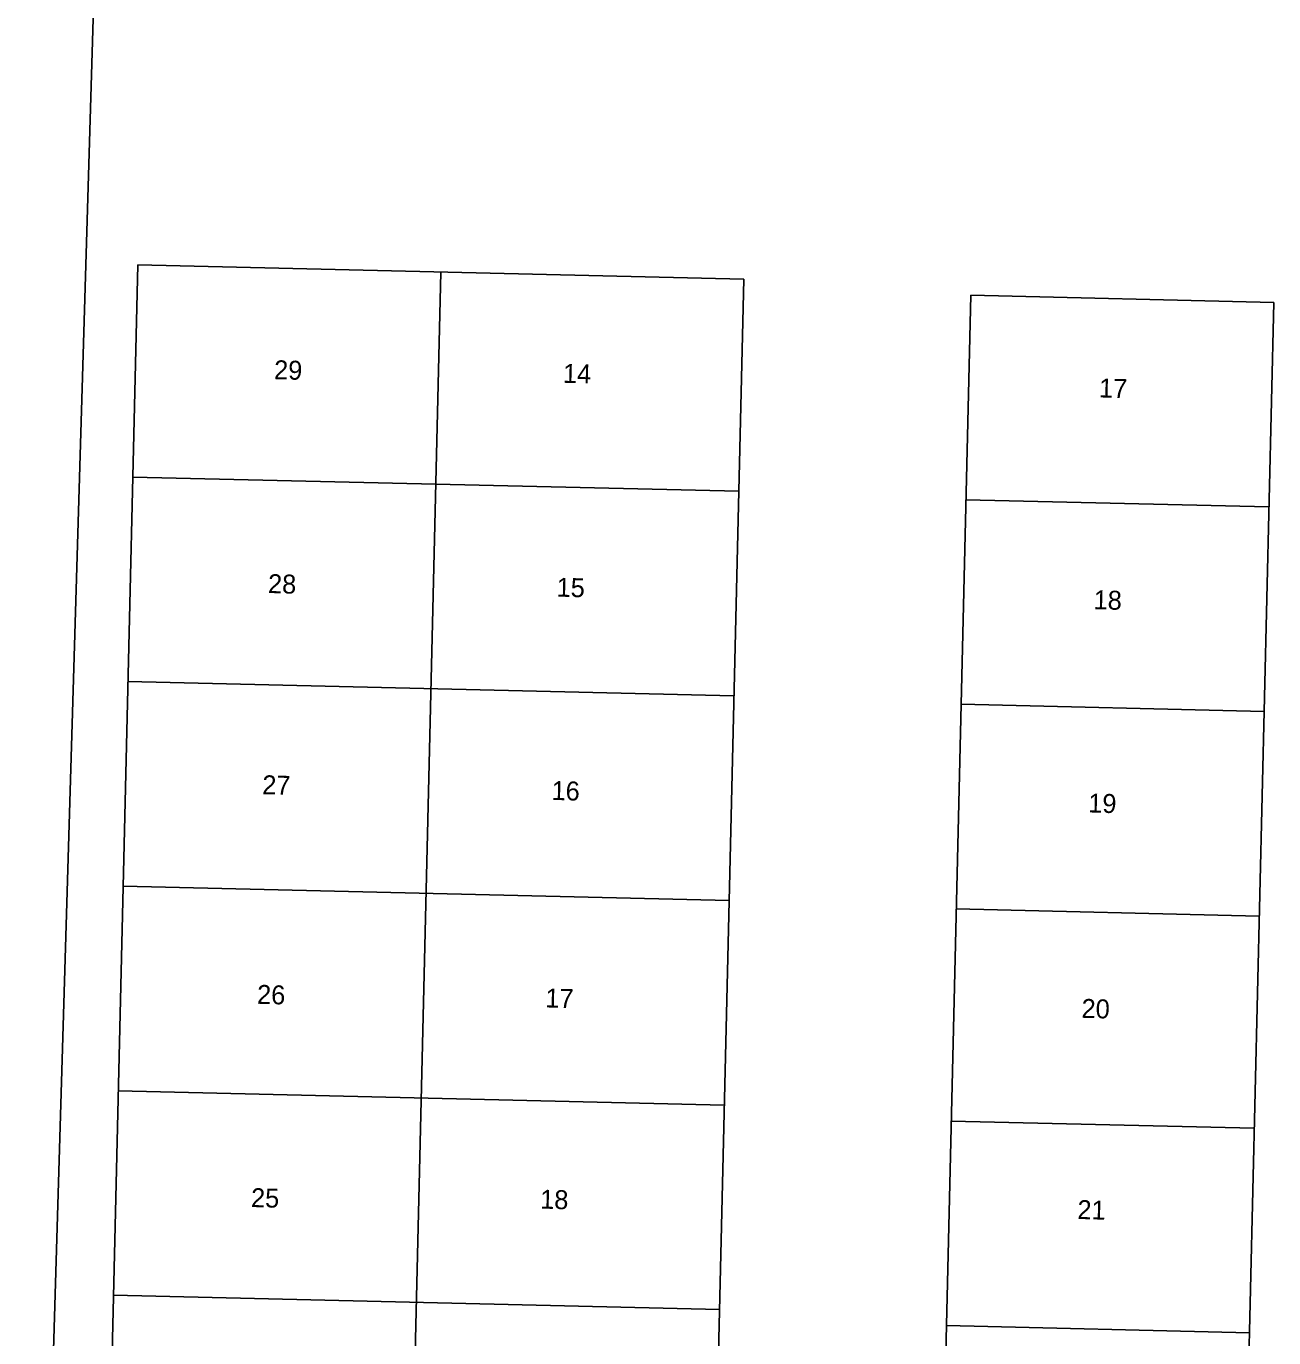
# Model space of a CAD drawing. Extents: x 7581380 to 7602708, y 543740 to 556109.
# Drawn here: x 7590878.1 to 7591207.4, y 550533.2 to 550879.3 of the extents above; entities that cross this region are included whole.
import ezdxf

# ---------------------------------------------------------------- set-up
doc = ezdxf.new("R2010")
doc.units = 0
for name, color, linetype in [('E_SURV_BNDRY_CROW', 7, 'Continuous'), ('E_SURV_BNDRY_GovSixSectLine', 7, 'Continuous'), ('E_SURV_BNDRY_Property', 7, 'Continuous'), ('E_SURV_BNDRY_SubdivisionTx', 7, 'Continuous')]:
    doc.layers.add(name, color=color, linetype=linetype)

msp = doc.modelspace()

# ---------------------------------------------------------------- linework, layer by layer
at = {"layer": 'E_SURV_BNDRY_CROW'}
for p, q in [((7590897.19, 550378.47), (7590907.53, 550816.31)), ((7591057.06, 550370.62), (7591067.5, 550812.53)), ((7591117, 550367.67), (7591127.41, 550808.31))]:
    msp.add_line(p, q, dxfattribs=at)
at = {"layer": 'E_SURV_BNDRY_GovSixSectLine'}
msp.add_lwpolyline([(7590878.09, 550287.75), (7590917.05, 551595.92)], dxfattribs=at)
at = {"layer": 'E_SURV_BNDRY_Property'}
for p, q in [((7590907.53, 550816.31), (7591067.5, 550812.53)), ((7590977.12, 550374.54), (7590987.51, 550814.42)), ((7591207.39, 550806.42), (7591127.41, 550808.31)), ((7590906.2, 550760.32), (7591066.16, 550756.55)), ((7591206.12, 550752.44), (7591126.14, 550754.33)), ((7590904.92, 550706.34), (7591064.89, 550702.57)), ((7591204.84, 550698.45), (7591124.86, 550700.34)), ((7590903.65, 550652.35), (7591063.61, 550648.58)), ((7591203.57, 550644.47), (7591123.59, 550646.36)), ((7590902.38, 550598.37), (7591062.34, 550594.6)), ((7591202.25, 550588.49), (7591122.26, 550590.37)), ((7590901.1, 550544.38), (7591061.07, 550540.61)), ((7591200.97, 550534.5), (7591120.99, 550536.39))]:
    msp.add_line(p, q, dxfattribs=at)
msp.add_lwpolyline([(7591207.39, 550806.42), (7591196.94, 550363.75)], dxfattribs=at)

# ---------------------------------------------------------------- texts
at = {"layer": 'E_SURV_BNDRY_SubdivisionTx'}
for s, p in [('29', (7590943.46, 550786.16)), ('14', (7591019.71, 550785.2)), ('17', (7591161.22, 550781.34)), ('28', (7590941.86, 550729.72)), ('15', (7591018.03, 550728.77)), ('18', (7591159.78, 550725.46)), ('27', (7590940.34, 550676.64)), ('16', (7591016.7, 550675.12)), ('19', (7591158.37, 550671.82)), ('26', (7590938.97, 550621.32)), ('17', (7591015.07, 550620.36)), ('20', (7591156.6, 550617.62)), ('25', (7590937.37, 550567.68)), ('18', (7591013.7, 550567.27)), ('21', (7591155.51, 550564.53))]:
    msp.add_text(s, height=5, rotation=358.4384, dxfattribs=at).set_placement(p)

doc.saveas('drawing.dxf')
